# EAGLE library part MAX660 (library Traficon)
Charge-pump VOLTAGE CONVERTER
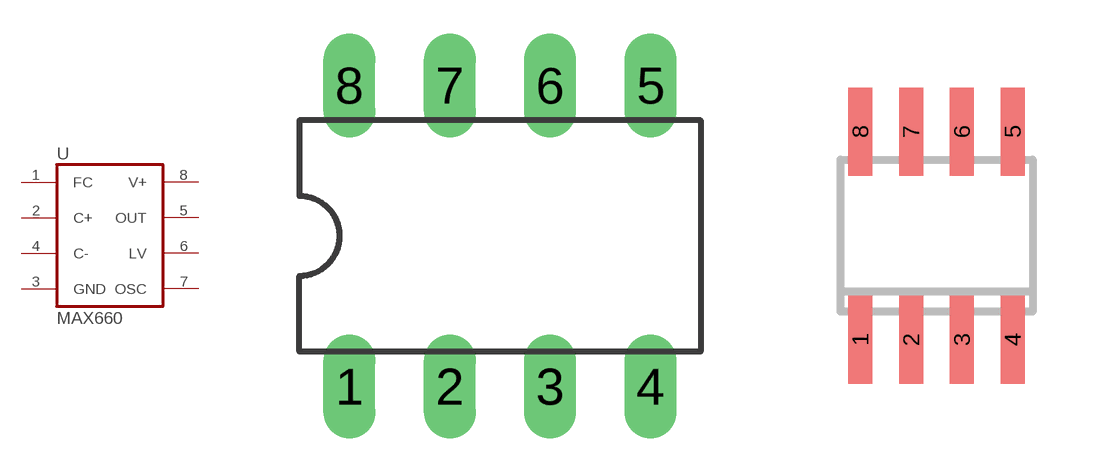
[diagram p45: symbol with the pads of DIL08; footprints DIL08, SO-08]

Designator prefix U

## MAX660CPA  [DIL08]
1  FC  in
2  C+  pas
3  GND  pwr
4  C-  pas
5  OUT  sup
6  LV  pas
7  OSC  out
8  V+  pwr

## MAX660M  [SO-08]
Pads as for DIL08

## Footprint DIL08 (pad centres in mm)
Dual In Line Package
drill 0.813 long: 1 -3.81,-3.81; 2 -1.27,-3.81; 3 1.27,-3.81; 4 3.81,-3.81; 5 3.81,3.81; 6 1.27,3.81; 7 -1.27,3.81; 8 -3.81,3.81

## Footprint SO-08 (pad centres in mm)
smd 0.6 x 2.2: 1 -1.905,-2.6; 2 -0.635,-2.6; 3 0.635,-2.6; 4 1.905,-2.6; 5 1.905,2.6; 6 0.635,2.6; 7 -0.635,2.6; 8 -1.905,2.6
